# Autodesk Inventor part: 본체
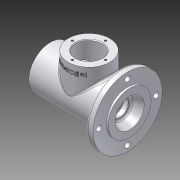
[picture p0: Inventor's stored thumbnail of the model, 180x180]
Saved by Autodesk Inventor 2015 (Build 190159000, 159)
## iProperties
Created: 2016-08
Part Number: 본체
Material: 알루미늄 6061
Document SubType Name: Modeling
Designer: owner
Density: 2.71 g/cm^3
Appearance: 알루미늄 - 평지
Mass: 730.585 g
Surface Area: 615.716 cm^2
Volume: 269.589 cm^3
Author: owner
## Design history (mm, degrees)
sketch "스케치1"
  geometry: C1 r 31 at (0, 0); 1 further point
  constraints: 1 centre point, 1 coincident
  dimensions: "d0" = 62 diameter of C1
extrude "돌출1" new body sketch "스케치1" stored distance "d1" = 115; taper "d2" = 0 deg
node "작업 평면1"
sketch "스케치2"
  geometry: C1 r 50 at (0, 0); 1 further point
  constraints: 1 centre point, 1 coincident
  dimensions: "d4" = 100 diameter of C1
extrude "돌출2" join sketch "스케치2" distance "d5" = 10; taper "d6" = 0 deg
sketch "스케치4"
  geometry: L1 (57.5, 0)-(-57.5, 0); L2 (57.5, -31)-(57.5, 31) reference; L3 (-57.5, 31)-(-57.5, -31) reference; L4 (48.5, 0)-(48.5, 24); L5 (48.5, 24)-(45.5, 24); L6 (45.5, 24)-(45.5, 20); L7 (45.5, 20)-(36.5, 20); L8 (36.5, 20)-(36.5, 17.5); L9 (36.5, 17.5)-(33.25, 17.5); L10 (33.25, 17.5)-(33.25, 18.5); L11 (33.25, 18.5)-(31.5, 18.5); L12 (31.5, 18.5)-(31.5, 17.5); L13 (31.5, 17.5)-(20.5, 17.5); L14 (20.5, 17.5)-(20.5, 26); L15 (20.5, 26)-(-17.5, 26); L16 (-17.5, 26)-(-17.5, 17.5); L17 (-17.5, 17.5)-(-28.5, 17.5); L18 (-28.5, 17.5)-(-28.5, 16.5); L19 (-28.5, 16.5)-(-33.5, 16.5); L20 (-33.5, 16.5)-(-33.5, 10); L21 (-33.5, 10)-(-36.2, 10); L22 (-36.2, 10)-(-36.2, 12.5); L23 (-36.2, 12.5)-(-43.5, 12.5); L24 (-43.5, 12.5)-(-43.5, 16); L25 (-43.5, 16)-(-57.5, 21); 1 further point
  constraints: 46 end point, 17 parallel, 4 perpendicular, 3 midpoint, 2 point on line, 1 collinear, 1 horizontal
  dimensions: "d7" = 48 diameter of L5 L1; "d8" = 40 diameter of L7 L1; "d9" = 35 diameter of L9 L1; "d10" = 37 diameter of L11 L1; "d11" = 35 diameter of L13 L1; "d12" = 52 diameter of L15 L1; "d13" = 33 diameter of L19 L1; "d14" = 20 diameter of L21 L1; "d15" = 25 diameter of L23 L1; "d16" = 32 diameter of L24.end L1; "d17" = 42 diameter of L25.end L1; "d18" = 14 horizontal distance of L25.end L24.end; "d19" = 7.3 distance of L22.end L23.end; "d20" = 2.7 distance of L20.end L21.end; "d21" = 5 distance of L18.end L19.end; "d22" = 38 distance of L14.end L15.end; "d23" = 60 distance of L12.end L17.end; "d24" = 11 distance of L16.end L17.end; "d25" = 1.75 distance of L10.end L11.end; "d27" = 3 distance of L4.end L5.end; "d29" = 12 distance between parallel lines of L2 L6; "d30" = 21 distance between parallel lines of L2 L8
revolve "회전1" sketch "스케치4" stored, may be unused: angle "d31" = 90 deg
node "작업 평면2"
sketch "스케치5"
  geometry: L1 (-57.5, 31)-(-57.5, -31) reference; L2 (0, 0)-(-57.5, 0); C1 r 30 at (-1.5, 0)
  constraints: 2 end point, 1 centre point, 1 midpoint, 1 point on line
  dimensions: "d33" = 60 diameter of C1; "d34" = 56 distance from line of L1 C1.centre
extrude "돌출3" join sketch "스케치5" stored distance "d35" = 10; taper "d36" = 0 deg
hole "구멍2" diameter "d48" = 40.376; stored, may be unused: countersink angle "d52" = 90 deg, drill point angle "d54" = 0 deg; dims "d46" = 10, "d47" = 10, "d49" = 9, "d50" = 4, "d51" = 2, "d53" = 9
sketch "스케치6" dims "d55" = 48
  geometry: L1 (0, 0)-(0, 24); C1 r 30 at (0, 0) reference; 2 further points
  constraints: 2 coincident, 2 end point, 1 vertical, 1 vertical alignment, 2 other
hole "구멍3" sketch "스케치6" at (0, 24) diameter "d56" = 3.242; stored, may be unused: countersink angle "d60" = 90 deg, drill point angle "d62" = 118 deg; dims "d57" = 8, "d58" = 4, "d59" = 2, "d61" = 10
sketch "스케치7" dims "d66" = 83
  geometry: L1 (0, 0)-(0, 41.5); C1 r 31 at (0, 0) reference; 1 further point
  constraints: 2 coincident, 2 end point, 1 vertical, 1 vertical alignment, 2 other
hole "구멍4" sketch "스케치7" at (0, 41.5) diameter "d67" = 8; stored, may be unused: countersink angle "d71" = 90 deg, drill point angle "d73" = 0 deg; dims "d68" = 8, "d69" = 4, "d70" = 2, "d72" = 10
node "작업 평면3"
sketch "스케치8"
  geometry: L1 (-57.5, 31)-(-57.5, -31) reference; L2 (-31.5, 49)-(28.5, 49) reference; 2 further points
  constraints: 1 other
  dimensions: "d78" = 56 distance from line of L1 point (-1.5, 39); "d79" = 10 distance from line of L2 point (-1.5, 39)
feature "엠보싱1" sketch "스케치8" dims "d80" = 0.5, "d81" = 0
chamfer "모따기1" distance "d82" = 1; stored, may be unused: second distance "d83" = 2, angle "d84" = 45 deg
chamfer "모따기2" distance "d85" = 0.7; stored, may be unused: second distance "d86" = 2, angle "d87" = 30 deg
fillet "모깎기1" dims "d88" = 0.3, "d89" = 3
sketch "스케치9"
  geometry: C1 r 30 at (0, 0) reference; C2 r 19 at (0, 0); 1 further point
  constraints: 1 centre point, 1 coincident
  dimensions: "d92" = 38 diameter of C2
extrude "돌출4" cut sketch "스케치9" distance "d93" = 49; taper "d94" = 0 deg
chamfer "모따기3" distance "d98" = 1; stored, may be unused: second distance "d99" = 2, angle "d100" = 30 deg
node "솔리드1"
pattern_circular "원형 패턴2" dims angle "d75" = 360 deg
pattern_circular "원형 패턴3" dims angle "d96" = 360 deg
other parameters: "d3" = -3, "d32" = 49, "d77" = -55.75
